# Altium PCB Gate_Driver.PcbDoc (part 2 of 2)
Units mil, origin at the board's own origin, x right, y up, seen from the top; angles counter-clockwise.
Board outline 1574.8 x 1574.8 mil, 2 copper layers (Top Layer, Bottom Layer), stack 62 mil thick; 111 components, 52 nets, 273 pads, 84 vias.
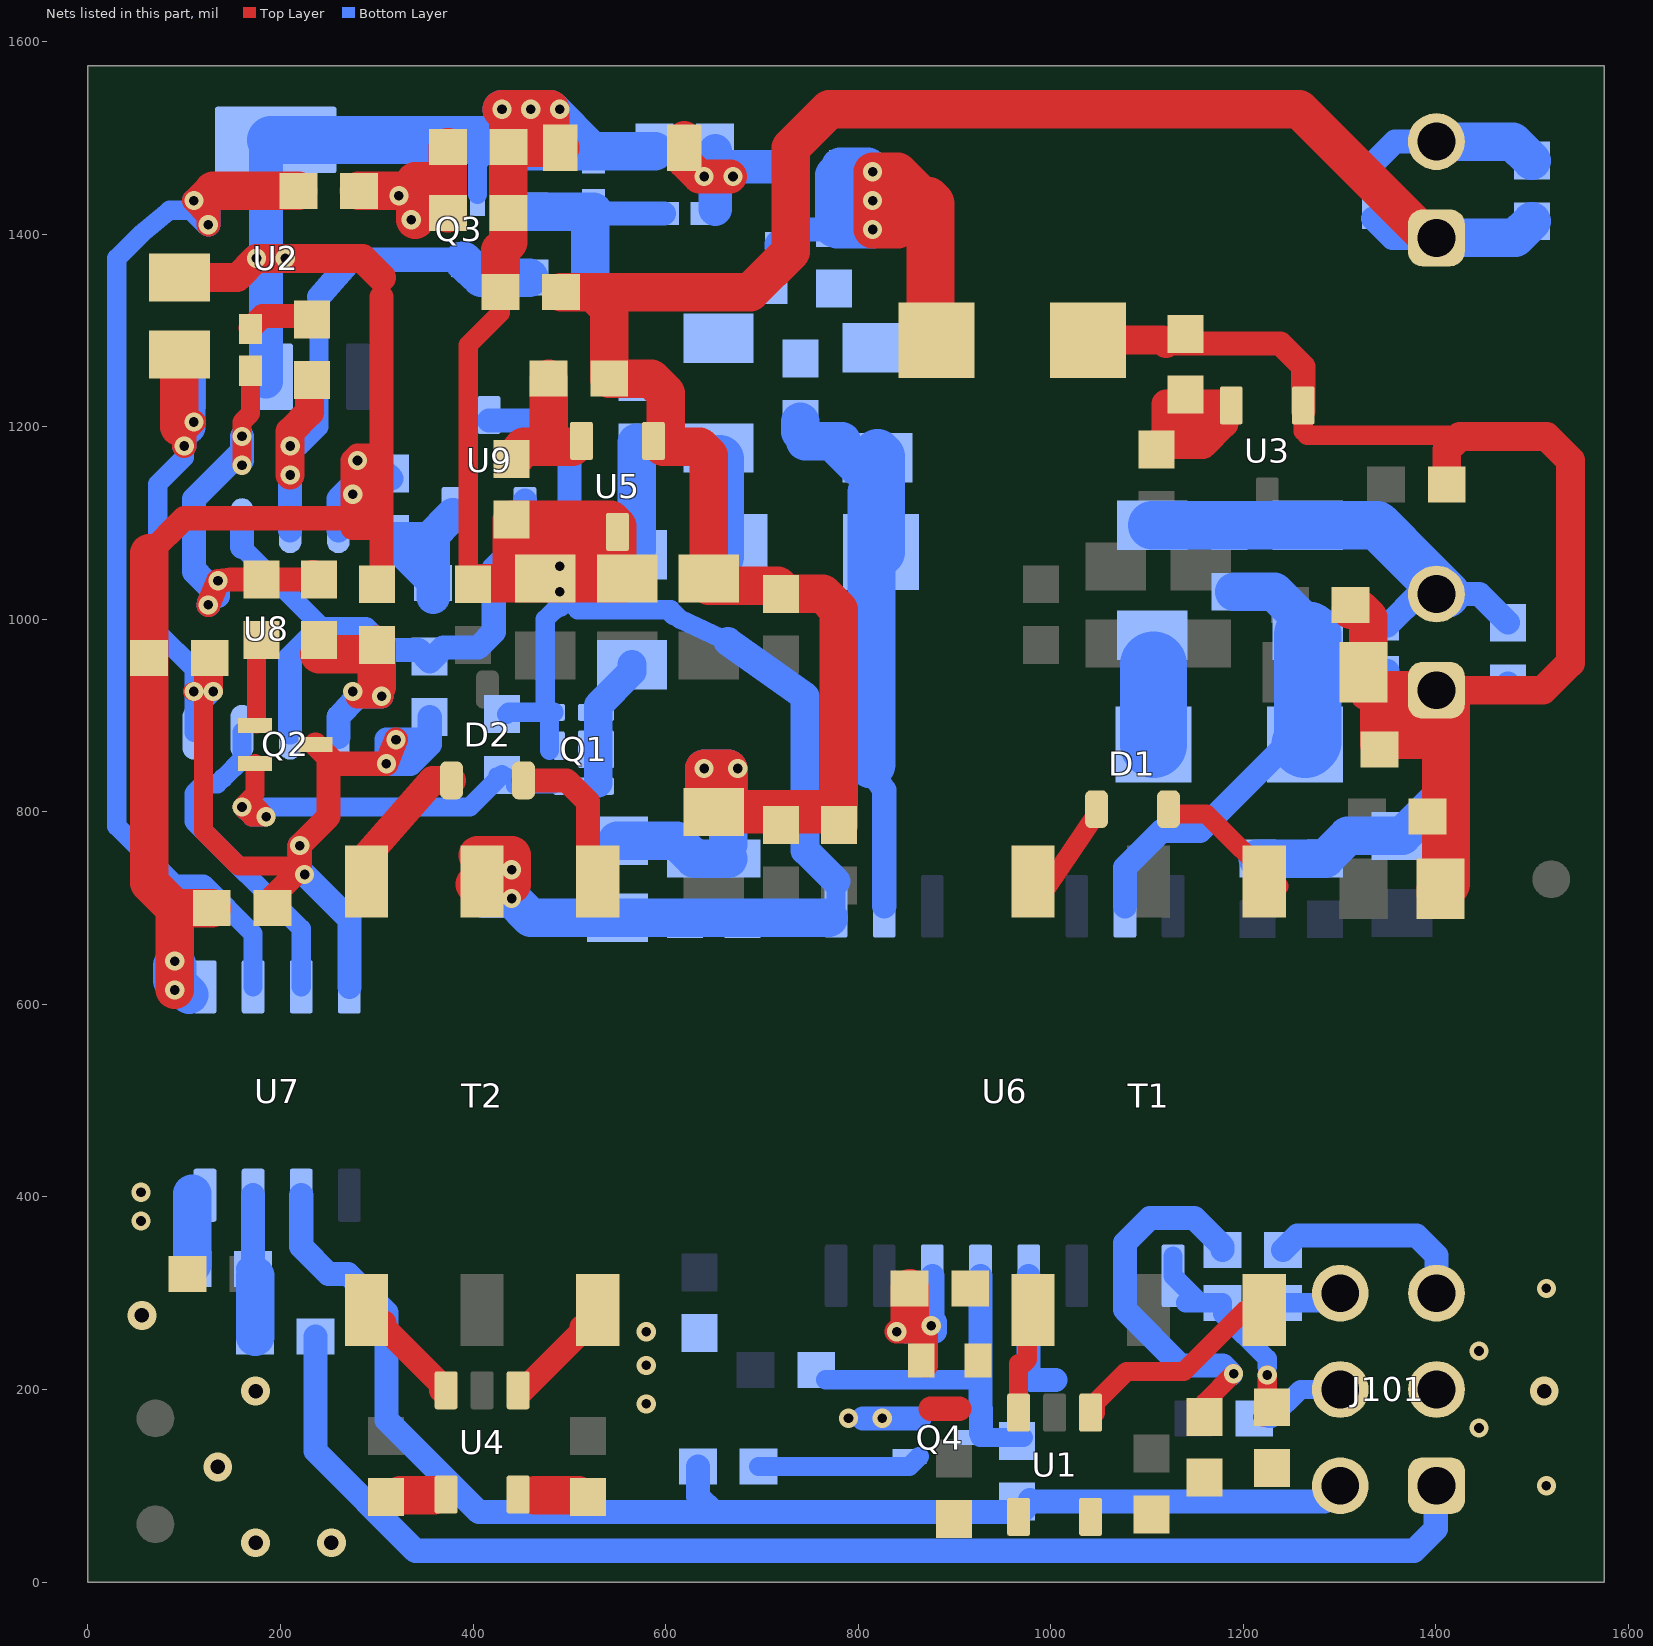
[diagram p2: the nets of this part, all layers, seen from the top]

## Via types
v1: diameter 20, hole 10, Top Layer to Bottom Layer, 78 vias
v2: diameter 30, hole 15, Top Layer to Bottom Layer, 6 vias

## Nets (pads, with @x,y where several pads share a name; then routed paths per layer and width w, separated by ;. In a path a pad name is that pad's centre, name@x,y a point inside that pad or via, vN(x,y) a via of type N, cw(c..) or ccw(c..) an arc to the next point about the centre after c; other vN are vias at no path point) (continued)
-4Vb: C7.2 C12.2 C13.2 C14.2 C15.2 C26.1 C27.1 C30.1 C33.2 C34.2 C36.2 C37.2 C38.2 D9.2 Q1.4 Q1.7 Q3.2 R6.1 R19.2 R25.1 R26.1 R28.1 R29.1 T2.5 U2.2 U2.4 U5.3 U6.9 U7.5 U8.4 U9.3 | length 5391.6
  Top Layer w20: C14.2@400,1036.5 395,1041.5 395,1285 428.5,1318.5 C15.2@428.5,1340
  Top Layer w25: 63.5,1068.5 100,1105 ; 105,1105 275,1105 ; C36.2@300,1036.5 305,1041.5 305,1095 ; 305,1335 305,1170 ; v1(275,1130) 290,1145 ; v1(275,1130) 290,1115 290,1095 ; v1(275,1130) 275,1145 ; v1(275,1130) 275,1095 290,1095 ; 275,1145 290,1145 ; 275,1145 275,1165 280,1170 305,1170 ; 290,1095 305,1095 ; 290,1145 305,1145 ; 305,1095 305,1145 ; 305,1145 305,1170
  Top Layer w30: C7.2@95,1355 155,1355 v1(175,1375) v1(205,1375) 285,1375 305,1355
  Top Layer w40: 63.5,1068.5 C37.2@63.5,960 63.5,726.5 90,700 ; v1(90,615) 90,700 ; C33.2@128.5,700 90,700 ; T2.5@402.01,725 440,725 440,755 T2.5@405,755 ; C14.2@405.95,1037.44 C13.2@445,1037.44 ; C15.2@428.5,1340 428.5,1383.5 436.77,1391.77 C38.2@436.77,1421.89 R29.1@436.77,1490.59 ; R29.1@436.77,1480.59 446.18,1490 D9.2@490.53,1490 D9.2@489.94,1490.59 ; R29.1@436.77,1490.59 D9.2@489.94,1490.59 ; R29.1@436.77,1490.59 436.77,1523.23 v1(430,1530) 455,1530 480,1530 480,1500.53 D9.2@489.94,1490.59 ; 440,1073.98 R6.1@440,1103.5 543.23,1103.5 U5.3@550,1096.73 ; 440,1073.98 440,1042.44 C13.2@445,1037.44 ; 440,1073.98 527.24,1073.98 U5.3@550,1096.73 ; C13.2@445,1037.44 557.56,1037.44 550,1045 U5.3@550,1096.73
  Bottom Layer w20: Q3.2@404.69,1441.5 404.69,1474.69 416.5,1486.5 R25.1@458.5,1486.5 ; R19.2@435,901.46 436.93,903.39 Q1.4@484,903.39 ; 475,906.34 475,1000 490,1015 ; 479.41,863.74 479.41,898.39 ; v1(490,1028.7) 508.7,1010 602.16,1010 ; 608.66,1003.5 602.16,1010 ; 665,976.85 615.28,1000 605.28,1010 602.16,1010 ; U6.9@777.13,701.93 U6.9@777.13,727.87 ; 410,720 430,720 v1(440,710) ; 410,720 410,700 430,700 v1(440,710) ; 410,720 410,750 420,740 v1(440,740) v1(440,710)
  Bottom Layer w25: U8.4@260,1092.28 260,1125 280,1145 ; 280,1150 280,1145 ; 280,1155 306.5,1155 315,1146.5 291.5,1146.5 280,1135 280,1145 ; U9.3@416.57,1206.34 473.07,1206.34 500,1179.41 500,1065 v1(490,1055) v1(490,1028.7) 490,1015
  Bottom Layer w30: v1(175,1375) 185,1375 v1(205,1375) ; 665,976.85 745,920 745,760 U6.9@777.13,727.87
  Bottom Layer w35: U2.2@185,1246.97 185,1375 U2.4@185,1493.03
  Bottom Layer w40: 90,625 105,610 ; v1(430,1530) 455,1530 480,1530 523.5,1486.5 C34.2@525,1486.5 ; v1(440,710) 460,690 465,690 C26.1@550,690 620,690 680,690 U6.9@769.71,690 ; R25.1@458.5,1486.5 R25.1@458.5,1486.5 R26.1@588.5,1486.46
  Bottom Layer w45: 90,625 v1@90,640
  Bottom Layer w50: U2.4@190,1498.03 U2.4@195,1498.03 R25.1@451.97,1498.03
  other v1: 90,645 280,1165 460,1530 490,1530
Coma: C1.2 C8.1 C16.1 C17.1 C18.1 C19.1 C20.1 C21.1 C39.2 D6.1 J103.1 R1.1 R2.2 R12.1 U3.1 | length 2048.7
  Top Layer w20: U3.1@1262.4,1216.34 1262.4,1195.28 1266.34,1191.34 1413.66,1191.34 1420,1185
  Top Layer w25: 1120,1286.5 1238.5,1286.5 1262.4,1262.6 U3.1@1262.4,1216.34
  Top Layer w30: D6.1@1038.74,1290 1116.5,1290 1120,1286.5 ; J103.1@1410.63,926.3 1511.3,926.3 1539.8,954.8 1539.8,1165.2 1515,1190 1425,1190 1420,1185 1411.5,1176.5 C8.1@1411.5,1140
  Top Layer w40: C1.2@1311.5,1010 1321.5,1010 1330,1001.5 R1.1@1330,935 ; R1.1@1325,940 R1.1@1330,935 ; R1.1@1330,925 R1.1@1330,935 ; R1.1@1336.5,928.5 R1.1@1330,935 ; C21.1@1341.5,870 C21.1@1341.5,875 ; R1.1@1341.5,928.5 1341.5,900 ; 1352.8,926.3 J103.1@1410.63,926.3 ; 1410,875 C21.1@1341.5,875 ; 1410.63,896.3 1406.93,900 1341.5,900 ; C21.1@1341.5,875 1341.5,900
  Top Layer w50: C16.1@1405,715 C16.1@1405,720 1410.63,725.63 1410.63,896.3 J103.1@1410.63,926.3
  Bottom Layer w25: C39.2@1350,946.38 1350,941.3 1365,926.3 1467.8,926.3 R12.1@1475,933.5
  Bottom Layer w40: C20.1@1215,751.5 C19.1@1285,751.5 1308.5,775 C18.1@1365,775 1410.63,820.63 J103.1@1410.63,925.67
Comb: C9.2 C15.1 C26.2 C27.2 C28.2 C29.2 C30.2 C31.2 C40.2 J102.1 R4.1 R5.2 R14.1 U5.1 | length 2536.4
  Top Layer w30: C15.1@510.87,1339.21 511.65,1340 ; 527.87,1340 529.37,1338.5
  Top Layer w40: C15.1@491.5,1340 511.65,1340 524.49,1340 ; C28.2@640,810 v1(640,845) 665,845 665,815 C28.2@650,800 ; C9.2@720,1026.5 763.5,1026.5 780,1010 C31.2@780,786.5 ; C9.2@725,1026.5 716.5,1035 645,1035 645,1170 635.59,1179.41 597.4,1179.41 600,1182.01 600,1235 585,1250 R5.2@541.5,1250 541.5,1322.99 524.49,1340 ; J102.1@1410.63,1396.3 1391.89,1396.3 1258.19,1530 770,1530 730,1490 730,1381.87 688.13,1340 527.87,1340 524.49,1340
  Top Layer w45: C28.2@650,800 C31.2@770,800
  Bottom Layer w25: C40.2@1335,1416.38 1355.08,1396.3 J102.1@1410.63,1396.3
  Bottom Layer w40: C26.2@550,770 611.5,770 630,751.5 C27.2@665,751.5 ; v1(640,845) 665,845 C27.2@665,766.5 ; J102.1@1410.63,1396.3 1482.8,1396.3 R14.1@1500,1413.5
  other v1: 675,845
FLT: J101.2 R31.1 R32.2 U7.2 | length 1380
  Bottom Layer w25: U7.2@221.5,401.73 221.5,348.5 250,320 270,320 310,280 310,168.5 406,72.5 650,72.5 ; R32.2@633.5,120 633.5,89 650,72.5 ; R31.1@978.5,85 R31.1@980,83.5 ; J101.2@1300.82,100 1284.32,83.5 R31.1@980,83.5 ; 650,72.5 969,72.5 R31.1@980,83.5
G1: C23.2 C39.1 J103.2 R7.2 R8.2 R12.2 | length 485.1
  Bottom Layer w25: C39.1@1350,993.62 1383.46,1027.09 1383.46,1053.46 ; J103.2@1410.63,1026.3 1445.2,1026.3 R12.2@1475,996.5
  Bottom Layer w50: R8.2@1105.55,1097.76 R7.2@1267.05,1097.76 1339.17,1097.76 1383.46,1053.46 J103.2@1410.63,1026.3
G2: C24.2 C25.1 C40.1 D5.1 J102.2 R10.2 R11.2 R14.2 R15.2 | length 182.6
  Bottom Layer w25: C40.1@1335,1473.62 1357.68,1496.3 J102.2@1410.63,1496.3
  Bottom Layer w40: J102.2@1410.63,1496.3 1480.2,1496.3 R14.2@1500,1476.5
GND: C2.2 C3.2 C10.2 C11.2 C22.2 C32.2 C35.2 C41.2 C42.2 C43.2 J101.3 Q4.2 R9.2 U1.4 U1.5 U4.4 U4.5 U6.4 U7.4 | length 376.9
  Top Layer w25: 875,180 905.47,180
  Top Layer w40: C11.2@324.37,90 359.37,90 ; 464.37,90 C10.2@509.37,90
  Bottom Layer w25: 805,170 805.31,169.69 Q4.2@863.5,169.69 ; U6.4@977.13,318.07 977.13,212.87 980,210 1005,210
  Bottom Layer w40: C35.2@108.5,330 108.5,403.5
  other v1: 1515,100 1445,160 790,170 825,170 580,185 580,225 1445,240 580,260 1515,305 55,375 55,405
  other v2: 174.14,40.8 252.88,40.8 134.77,119.54 174.14,198.28 1512.73,198.28 56.03,277.02
NetC23_1: C23.1 D3.1 R7.1 U6.15 | length 496.2
  Bottom Layer w25: U6.15@1077.13,701.93 1077.13,742.13 1115,780 1155,780 1245,870 D3.1@1264.29,870
  Bottom Layer w30: R7.1@1267.05,983.58 R7.1@1267.05,993.78
  Bottom Layer w40: C23.1@1190.55,1028.68 1232.15,1028.68 R7.1@1267.05,993.78
  Bottom Layer w70: D3.1@1264.29,870 1267.05,872.76 R7.1@1267.05,983.58
NetC24_1: C24.1 D4.1 R10.1 U6.10 | length 626.2
  Bottom Layer w25: 808.74,849.49 827.13,822.87 U6.10@827.13,701.93
  Bottom Layer w40: C24.1@740,1195 C24.1@740,1205.06 ; 745,1185 772.91,1185 ; 782.91,1185 772.91,1185 ; R10.1@800,1157.91 772.91,1185
  Bottom Layer w50: 813.74,849.49 813.74,1131.65 ; R10.1@820,1172.91 823.74,1169.17 D4.1@823.74,1070
NetC25_2: C25.2 R13.2 | length 118.5
  Bottom Layer w40: R13.2@565,1067.09 570,1072.09 C25.2@570,1183.5
NetC34_1: C34.1 D8.1 R21.2 R25.2 | length 210.6
  Bottom Layer w25: C34.1@525,1423.5 527.05,1421.46 D8.1@598.35,1421.46
  Bottom Layer w40: R25.2@458.5,1423.5 525,1423.5 521.5,1420 R21.2@521.5,1355
NetC35_1: C35.1 R23.2 U7.3 | length 141.8
  Bottom Layer w25: C35.1@166.5,325 171.5,330 U7.3@171.5,401.73
  Bottom Layer w40: R23.2@173.5,255 C35.1@173.5,317.99
NetC36_1: C36.1 R22.2 U8.5 | length 205.7
  Top Layer w25: v1@280,920 v1(305,920) ; 295,925 300,930
  Top Layer w40: R22.2@240,963.5 C36.1@295,963.66 ; 300,930 C36.1@300,973.5
  Bottom Layer w25: U8.5@260,877.72 U8.5@260,882.72 260,898.31 280,920 v1(305,920)
  other v1: 275,925
NetC38_1: C38.1 Q3.1 R27.2 R29.2 | length 351
  Top Layer w40: R27.2@281.5,1445 338.78,1445 346.89,1436.89 C38.1@373.78,1436.89 ; v1@340,1415 340,1440 ; 340,1455 364.62,1455 ; C38.1@364.62,1440 373.78,1449.16 ; C38.1@373.78,1421.89 373.78,1449.16 ; R29.2@373.78,1490.59 373.78,1449.16
  Bottom Layer w20: v1(322.95,1440) 335.75,1427.2 ; v1(335.75,1415) 335.75,1427.2 ; 335.75,1440 335.75,1427.2 ; Q3.1@361.81,1440 340,1440 340,1415 343.82,1415 Q3.1@365.32,1436.5
NetC41_1: C41.1 R34.1 U6.2 | length 377.6
  Top Layer w20: C41.1@1160,186.28 v1(1190,216.28)
  Bottom Layer w25: R34.1@1178.5,345 1178.5,348.7 1149.15,378.05 1103.05,378.05 1077.13,352.13 U6.2@1077.13,318.07 1077.13,282.87 1135,225 1178.78,225 v1@1187.5,216.28
NetC42_1: C42.1 R33.1 U6.1 | length 238.2
  Top Layer w20: C42.1@1220,171.5 1225,176.5 v1(1225,215)
  Bottom Layer w10: v1(1225,215) v1@1225,223.7
  Bottom Layer w20: U6.1@1127.13,338.27 U6.1@1127.13,318.07 1155.2,290 ; 1140,290 1155.2,290 ; v1@1225,223.7 1225,231.81 1178.5,278.31 R33.1@1178.5,290 1155.2,290
NetC43_1: C43.1 R9.1 U6.6 | length 267.3
  Top Layer w25: 853.5,273.5 v1(840,260) 850,260 ; 855,270 853.5,268.5 850,265 850,260 ; R9.1@870,234.53 v1@870,260 ; v1@870,265 v1@870,260 ; R9.1@870.47,225 870.47,260.47 v1@870,260 ; 850,260 v1@870,260
  Top Layer w40: 853.5,268.5 853.5,273.5 C43.1@853.5,305
  Bottom Layer w25: 850,260 v1@877.13,260 ; v1@872.13,265 v1@875,265 ; U6.6@877.13,318.07 v1@877.13,267.13 ; v1@880,260 v1@877.13,260 ; v1@880,265 v1@877.13,265 ; v1@880,270 v1@877.13,267.13 ; v1@875,265 v1@877.13,265 ; v1@875,265 v1@877.13,267.13 ; v1@877.13,260 v1@877.13,265 ; v1@877.13,265 v1@877.13,267.13
  other v1: 876.06,266.06
NetD1_1: D1.1 T1.6 | length 90.7
  Top Layer w20: T1.6@996.69,722.64 D1.1@1047.6,797.76
NetD1_2: D1.2 T1.4 | length 145.6
  Top Layer w20: D1.2@1122.4,797.76 1161.73,797.76 T1.4@1236.85,722.64
NetD2_1: D2.1 T2.6 | length 150.6
  Top Layer w30: T2.6@289.29,727.64 289.29,754.29 357.76,832.76 D2.1@377.6,832.76
NetD2_2: D2.2 T2.4 | length 134.2
  Top Layer w25: D2.2@452.4,832.76 497.24,832.76 519.45,810.55 T2.4@519.45,752.64
NetD3_2: D3.2 R8.1 | length 82.6
  Bottom Layer w70: D3.2@1106.81,870 1106.81,952.6
NetD4_2: D4.2 R11.1 | length 101.7
  Bottom Layer w50: D4.2@656.26,1065 R11.1@656.26,1166.65
NetD5_2: D5.2 D6.2 R15.1 R18.2 | length 679
  Top Layer w40: 841.26,1405 v1(815,1405) v1(815,1435) v1(815,1465) 841.26,1465 ; 841.26,1405 841.26,1465 ; 841.26,1405 871.26,1435 841.26,1465
  Top Layer w50: 871.26,1435 875,1431.26 D6.2@875,1285
  Bottom Layer w25: D5.2@715,1386.65 715,1390 730,1405 771.5,1405 R15.1@775,1401.5 ; R18.2@781.5,1470 790,1461.5
  Bottom Layer w40: R15.1@775,1406.5 R18.2@775,1461.5 ; R15.1@778.5,1405 v1(815,1405) v1(815,1435) v1(815,1465) 810,1470 R18.2@781.5,1470
NetD7_1: D7.1 R17.1 | length 65.3
  Top Layer w25: D7.1@168.8,1302.58 181.22,1315 R17.1@229,1315
NetD7_2: D7.2 R16.1 R22.1 U8.1 | length 499.8
  Top Layer w20: v1(160,1160) 160,1205 168.8,1213.8 D7.2@168.8,1258.35 ; R22.1@232.5,1051.5 R22.1@235,1051.5
  Top Layer w25: v1(125,1015) v1@135,1039.45 ; v1(135,1040) 147.95,1041.5 R16.1@180,1041.5 R22.1@240,1041.5
  Bottom Layer w25: 110,1050 110,1049.45 135,1024.45 135,1039.45 v1(125,1015) ; 122.52,1039.45 110,1051.97 U8.1@110,1097.28 110,1125 160,1175 ; v1@160,1165 v1(160,1190)
NetD8_2: D8.2 D9.1 R18.1 R26.2 | length 217.1
  Top Layer w35: D9.1@619.47,1500 619.47,1475.53 635,1460 v1@667,1460
  Bottom Layer w25: v1(640,1460) 651.5,1460 v1@660,1460
  Bottom Layer w35: D8.2@651.5,1426.3 651.5,1460 R26.2@651.5,1486.46 ; 660,1470 R18.1@718.5,1470
  other v1: 670,1460
NetJ101_4: J101.4 R132.1 | length 86.7
  Bottom Layer w20: R132.1@1226.5,170 1229.5,170 1259.5,200 J101.4@1300.82,200
NetQ1_1: Q1.1 Q1.2 Q1.5 Q1.6 Q1.8 R13.1 | length 137.4
  Bottom Layer w30: 530,830 530,910.51 565,945.51 R13.1@565,952.91
NetQ1_3: Q1.3 Q2.2 R19.1 | length 502.2
  Top Layer w20: Q2.2@173.5,850.31 173.5,818.5 v1(160,805) ; v1(160,805) 175,805 v1(185,795) 170,795 v1(160,805)
  Bottom Layer w15: R19.1@423.47,838.47 R19.1@430,838.47 435,838.47 R19.1@446.85,826.61 ; R19.1@441.85,826.61 R19.1@446.85,826.61 ; Q1.3@484.41,826.61 R19.1@446.85,826.61
  Bottom Layer w20: 180,805 396.53,805 R19.1@430,838.47 ; v1(160,805) 175,805 v1(185,795) 170,795 v1(160,805)
NetQ2_1: Q2.1 R16.2 | length 87.3
  Top Layer w20: Q2.1@175,891.18 R16.2@175,978.5
NetQ3_3: Q3.3 R17.2 R21.1 U8.3 | length 596.8
  Top Layer w30: v1(210,1150) v1(210,1180) 210,1195 230,1215 230,1246 R17.2@232.5,1248.5
  Bottom Layer w20: 220,1180 240,1200 240,1335
  Bottom Layer w25: U8.3@210,1092.28 U8.3@210,1097.28 v1(210,1150) v1(210,1180) ; 240,1335 273.5,1373.5 Q3.3@385,1373.5
  Bottom Layer w40: Q3.3@390,1372.52 408.5,1355 R21.1@458.5,1355
NetQ4_1: Q4.1 R32.1 | length 171.3
  Bottom Layer w20: R32.1@696.5,120 853.19,120 Q4.1@863.5,130.32
NetQ4_3: Q4.3 R30.1 R31.2 U6.5 | length 368.7
  Bottom Layer w20: R30.1@766.5,210 927.13,210 ; Q4.3@926.5,150 R31.2@971.5,150
  Bottom Layer w25: U6.5@927.13,318.07 927.13,210 Q4.3@927.48,155
NetR2_1: R2.1 R3.2 U3.2 | length 256.9
  Top Layer w30: 1157.99,1212.71 1157.99,1207.99 ; 1173.5,1223.5 1120,1223.5 ; U3.2@1180,1203.5 1157.99,1181.5 ; 1120,1223.5 1138.5,1205 1155,1205 1157.99,1207.99 ; 1120,1223.5 1120,1191.5 1110,1181.5 1157.99,1181.5 ; 1157.99,1181.5 1157.99,1207.99
NetR5_1: R5.1 R6.2 U5.2 | length 127.4
  Top Layer w40: R6.2@445,1170 452.91,1179.41 U5.2@503,1179.41 ; 478.5,1185 R5.1@478.5,1250
NetR20_1: R20.1 R24.2 U8.2 U8.6 U9.1 | length 613.2
  Bottom Layer w20: U8.2@160,1075 240,995
  Bottom Layer w25: U8.2@160,1075 U8.2@160,1097.28 ; U8.6@210,882.72 210,960 240,990 288.35,990 310,968.35 343.15,968.35 355,956.5 369.06,970.55 405,970.55 421.5,987.05 R24.2@421.5,1037.8 421.5,1052.95 453.97,1085.43 U9.1@453.97,1123.66
NetR24_1: R24.1 R28.2 U9.2 | length 198.7
  Bottom Layer w35: R24.1@358.5,1022.8 R24.1@358.5,1040 ; U9.2@379.17,1108.66 354.01,1083.5 ; 354.01,1083.5 358.5,1079.01 R24.1@358.5,1040 ; 354.01,1083.5 315,1083.5 R24.1@358.5,1040
NetR27_1: R27.1 U7.6 | length 1200.7
  Top Layer w25: v1(125,1410) 125,1420 ; 125,1420 v1(110,1435) 120,1445 130,1445 125,1440 125,1420
  Top Layer w40: 130,1445 R27.1@218.5,1445
  Bottom Layer w20: 115,1425 110,1425 85,1425 55,1400 30,1375 30,785 90,725 120,725 171.5,673.5 U7.6@171.5,618.27
  Bottom Layer w25: v1(110,1435) 125,1435 125,1420 ; v1(110,1435) 125,1420 ; v1(110,1435) 110,1425 v1(125,1410) 125,1420
NetT1_1: T1.1 U1.3 | length 102.6
  Top Layer w20: U1.3@966.66,185.94 966.66,226.74 ; 971.66,226.74 976.02,231.11 976.02,271.69 T1.1@986.69,282.36
NetT1_3: T1.3 U1.1 | length 230.6
  Top Layer w20: U1.1@1046.46,175.94 1046.46,186.46 1078.68,218.68 1138.29,218.68 1201.97,282.36 T1.3@1226.85,282.36
NetT2_1: T2.1 U4.3 | length 118.3
  Top Layer w25: T2.1@289.29,272.36 289.29,269.34 T2.1@307.71,269.34 ; T2.1@302.71,269.34 366.97,205.08 U4.3@366.97,199.13
NetT2_3: T2.3 U4.1 | length 117.3
  Top Layer w25: U4.1@451.77,199.13 T2.3@517.72,265.08 ; T2.3@512.72,265.08 529.45,265.08 T2.3@529.45,272.36
NetU7_7: U7.7 U8.7 | length 339.9
  Bottom Layer w20: U8.7@160,882.72 160,854.5 140.5,835 140,835 134.17,829.17 120,829.17 110,819.17 110,790 221.5,678.5 U7.7@221.5,618.27
RESET: J101.1 R23.1 | length 1380
  Bottom Layer w25: R23.1@236.5,255 236.5,136 340,32.5 1377.5,32.5 1400,55 1400,99.18 J101.1@1400.82,100
Vcc5V: C7.1 C33.1 C37.1 Q2.3 R20.2 U2.3 U7.8 U8.8 | length 1496.5
  Top Layer w20: v1@108.5,925 v1(110,925) v1@120,925 ; C37.1@126.5,960 C37.1@120,953.5 ; v1@220,740 216.3,743.7 156.3,743.7 120,780 v1@120,925 ; v1@120,925 v1(130,925) 130,943.5 C37.1@120,953.5 ; v1@120,925 C37.1@120,953.5
  Top Layer w25: v1(100,1180) 100,1195 v1(110,1205) ; C33.1@191.5,700 191.5,711.5 220,740 v1(220,765) 250,795 250,850 ; Q2.3@236.5,870 256.5,850 v1(310,850) v1(320,875)
  Top Layer w40: 95,1200 C7.1@95,1255
  Bottom Layer w20: v1(100,1180) 100,1168.03 72.5,1140.53 72.5,986.42 110,948.92 v1(110,925) ; U8.8@110,882.72 U8.8@110,905 ; U8.8@110,905 v1(110,925) ; U8.8@110,905 v1(130,925) v1(110,925)
  Bottom Layer w25: v1(100,1180) 100,1195 104.45,1199.45 v1(110,1205) ; v1(220,765) 220,740 271.5,688.5 U7.8@271.5,618.27 ; 354.97,870.02 349.98,875 310,875 v1(310,850) 335,850 355,870 R20.2@355,898.5
  Bottom Layer w35: v1@104.45,1199.45 U2.3@104.45,1251.97
  other v1: 225,735
Vg1: J101.6 R33.2 | length 49.3
  Bottom Layer w20: R33.2@1241.5,290 J101.6@1290.82,290
Vg2: J101.5 R34.2 | length 213.3
  Bottom Layer w25: R34.2@1241.5,345 1256.5,360 1380,360 1400.82,339.18 J101.5@1400.82,300
pads on no net: FID1.1 FID2.1 FID3.1 Q1.0 U6.7

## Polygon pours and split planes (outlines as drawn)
G2 on Bottom Layer "BOTTOM_LAYER_G2_P000" (solid, remove dead copper, pour order 0): 555,1250 895,1250 935,1290 935,1355 1045,1465 1425,1465 1440,1480 1440,1515 1420,1535 1010,1535 875,1400 875,1375 855,1355 660,1355 625,1320 585,1320 555,1290
5Vin on Bottom Layer "BOTTOM_LAYER_5VIN_P004" (solid, remove dead copper, pour order 4): 315,430 405,340 765.87,340 775,330.87 775,290 770,285 668.7,285 653.7,300 505,300 465,260 370,260 355,275 355,320 300,375 265,375 255,385 255,425 260,430
GND on Bottom Layer "BOTTOM_LAYER_GND_P006" (solid, remove dead copper, pour order 6): 0,430 297.52,430 380,347.52 1572.28,347.52 1574.8,345 1574.8,5 0,5 0,420 0,425
Comb on Top Layer "TOP_LAYER_COMB_P014" (solid, remove dead copper, pour order 14): 798.54,770 808.54,780 808.54,1041.46 625,1225 625,1350 605,1370 481.3,1370 470,1358.7 470,1330 515,1285 515,1250 570,1195 570,1160 611.26,1118.74 611.26,788.74 630,770
Coma on Top Layer "TOP_LAYER_COMA_P012" (solid, remove dead copper, pour order 12): 1000,1250 1075,1250 1100,1275 1230,1275 1250,1255 1250,1195 1260,1185 1390,1185 1400,1175 1470,1175 1495,1150 1495,961.3 1488.7,955 1365,955 1350,970 1350,1005 1345,1005 1325,1025 1295,1025 1290,1020 1290,925 1320,895 1320,850 1325,845 1364.98,845 1369.98,840 1369.98,695.02 1380,685 1574.8,685 1574.8,1150.2 1520,1205 1340,1205 1218.98,1326.02 1000,1326.02
5Vin on Top Layer "TOP_LAYER_5VIN_P010" (solid, remove dead copper, pour order 10): 455,320 460,315 460,270 435,245 385,245 360,270 360,315 365,320
GND on Top Layer "TOP_LAYER_GND_P008" (solid, remove dead copper, pour order 8): 0,430 297.52,430 397.52,330 1574.8,330 1574.8,5 0,5 0,420 0,425

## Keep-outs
Keep-Out Layer:
  lines w10: 0,0 0,1574.8 1574.8,1574.8 1574.8,0 0,0 ; 65,470 65,540 1355,540 1355,470 65,470
  text ".Layer_Name" at 597,-858.49 h60

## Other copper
Top Layer:
  text ".Layer_Name" at 597,-858.49 h60
Bottom Layer:
  text ".Layer_Name" at 597,-858.49 h60

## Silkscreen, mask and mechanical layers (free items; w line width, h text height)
Top Overlay:
  lines w10: 10,500 50,500
  text "S2 G2" at 1340,1365 h35 r90
  text "S1 G1" at 1550,1105 h35 r90
  text ".Layer_Name" at 597,-858.49 h60
Bottom Overlay:
  lines w10: 10,500 50,500 ; 1375,500 1555,500
  text ".Layer_Name" at 597,-858.49 h60
Top Paste:
  text ".Layer_Name" at 597,-858.49 h60
Bottom Paste:
  text ".Layer_Name" at 597,-858.49 h60
Top Solder:
  text ".Layer_Name" at 597,-858.49 h60
  text ".Layer_Name" at 597,-858.49 h60
Bottom Solder:
  text ".Layer_Name" at 597,-858.49 h60
Drill Guide:
  text ".Layer_Name" at 597,-858.49 h60
M1 Board Outline:
  lines w10: 0,0 0,1574.8 1574.8,1574.8 1574.8,0 0,0 ; 65,470 65,540 1355,540 1355,470 65,470
  text ".Layer_Name" at 597,-858.49 h60
M2 Board Dimensions:
  rectangle: 20,-275 145,-150
  rectangle: 145,-400 520,-275
  lines w7: 20,-275 1020,-275 ; 145,-400 145,-150 ; 270,-400 270,-150 ; 520,-400 520,-150 ; 770,-400 770,-150 ; 20,-400 1020,-400 1020,-150 20,-150 20,-400
  text ".Layer_Name" at 597,-858.49 h60
M3 3D STEP Top:
  text ".Layer_Name" at 597,-858.49 h60
M4 3D STEP Bottom:
  text ".Layer_Name" at 597,-858.49 h60
M5 Assembly Top:
  lines w10: -272,-930.17 6328,-930.17 ; -272,-726.83 6330,-726.83 ; -272,-523.5 -272,-1133.5 3733,-1133.5 6330,-1133.5 6330,-523.5 -271.5,-523.5 -271.5,-1133.5 1304,-1133.5 ; 2193,-1133.5 2193,-523.5 ; 3460,-726.83 3460,-523.5 ; 4300,-726.83 4300,-523.5 ; 4922,-1140 4922,-937.17
  text "COMPONENTS MARKED 'DNP' SHOULD NOT BE POPULATED." at 1173.5,-318.5 h60
  text "ASSEMBLY VARIANT:" at 1173,-434 h60
  text ".VariantName" at 2209,-434 h60
  text "PCB VIEWED FROM TOP SIDE" at -208.5,-655.67 h60
  text "BOARD #:" at 2268,-655.67 h60
  text ".PRJ_Number" at 2813.5,-655.67 h60
  text "REV:" at 3658,-655.67 h60
  text ".PCB_Rev" at 3949.5,-655.67 h60
  text "SVN REV:" at 4496,-655.67 h60
  text ".VersionControl_RevNumber" at 5002,-655.67 h60
  text "TID #:" at 2268,-859 h60
  text ".TID" at 2813.5,-859 h60
  text "PLOT NAME =" at -208.5,-1064.34 h60
  text ".plot_File_Name" at 597,-1064.34 h60
  text "GENERATED    :" at 2270,-1064.34 h60
  text ".Print_Date" at 3139.5,-1064.34 h60
  text ".Print_Time" at 3868.5,-1064.34 h60
  text "TEXAS INSTRUMENTS" at 5133,-1064.34 h60
M6 Assembly Bottom:
  lines w10: -272.5,-727.33 6329.5,-727.33 ; -270.5,-930.67 6329.5,-930.67 ; 1135.5,-1140.5 1135.5,-937.67 ; 1757.5,-727.33 1757.5,-524 ; 2597.5,-727.33 2597.5,-524 ; 3864.5,-1134 3864.5,-524 ; 4753.5,-1134 6329,-1134 6329,-524 -272.5,-524 -272.5,-1134 2324.5,-1134 6329.5,-1134 6329.5,-524
  text "COMPONENTS MARKED 'DNP' SHOULD NOT BE POPULATED." at 6122,-318 h60
  text ".VariantName" at 5078,-434 h60
  text "ASSEMBLY VARIANT:" at 6117,-434 h60
  text ".VersionControl_RevNumber" at 1055.5,-656.17 h60
  text "SVN REV:" at 1561.5,-656.17 h60
  text ".PCB_Rev" at 2108,-656.17 h60
  text "REV:" at 2399.5,-656.17 h60
  text ".PRJ_Number" at 3244,-656.17 h60
  text "BOARD #:" at 3789.5,-656.17 h60
  text "PCB VIEWED FROM BOTTOM SIDE" at 6266,-656.17 h60
  text ".TID" at 3244,-859.5 h60
  text "TID #:" at 3789.5,-859.5 h60
  text "TEXAS INSTRUMENTS" at 924.5,-1064.84 h60
  text ".Print_Time" at 2189,-1064.84 h60
  text ".Print_Date" at 2918,-1064.84 h60
  text "GENERATED    :" at 3787.5,-1064.84 h60
  text ".plot_File_Name" at 5460.5,-1064.84 h60
  text "PLOT NAME =" at 6266,-1064.84 h60
M9 Title Sheet:
  drawing of 57 lines, arcs and shapes, not listed
  text "1" at 759.84,8036.5 h70
  text "2" at 3255.5,8036.5 h70
  text "3" at 5744.84,8036.5 h70
  text "4" at 8251.51,8036.5 h70
  text "5" at 10750.5,8036.5 h70
  text "6" at 13255.5,8036.5 h70
  text "A" at -396.5,6893.5 h70
  text "A" at 14403.5,6893.5 h70
  text "B" at -396.5,4513.5 h70
  text "B" at 14403.5,4513.5 h70
  text "C" at -396.5,2138.5 h70
  text "C" at 14403.5,2138.5 h70
  text "PROJECT TITLE:" at 11363.5,277.5 h45
  text ".PRJ_Title" at 11413.5,144.17 h70
  text "DESIGNED FOR:" at 11363.5,-23.5 h45
  text ".PRJ_Customer" at 11413.5,-163.5 h70
  text "D" at -396.5,-231.5 h70
  text "D" at 14403.5,-231.5 h70
  text "FILE NAME:" at 11363.5,-323.5 h45
  text ".PCB_File_Name_No_Path" at 11413.5,-443.5 h70
  text "Texas Instruments (TI) and/or its licensors do not warrant the accuracy or completeness of this specification" at 6394,-605.34 h45
  text "ENGINEER:" at 11363.5,-613.5 h45
  text "LAYOUT BY:" at 12868.5,-613.5 h45
  text "or any information contained therein. TI and/or its licensors do not warrant that this design will meet" at 6349.01,-718 h45
  text ".PRJ_Engineer" at 11413.5,-768.49 h70
  text ".PCB_Layout" at 12919,-768.49 h70
  text "the specifications, will be suitable for your application or fit for any particular purpose, or will operate in" at 6349.01,-830.67 h45
  text ".Layer_Name" at 597,-858.49 h60
  text "ALTIUM DESIGNER VERSION:" at 12868.5,-923.5 h45
  text "an implementation. TI and/or its licensors do not warrant that the design is production worthy. You should" at 6349.01,-943.33 h45
  text "completely validate and test your design implementation to confirm the system functionality for your application." at 6394,-1056 h45
  text ".print_Scale" at 11413.5,-1056.83 h70
  text ".Application_BuildNumber" at 12919,-1056.83 h70
  text "1" at 759.84,-1263.5 h70
  text "2" at 3255.5,-1263.5 h70
  text "3" at 5744.84,-1263.5 h70
  text "4" at 8251.51,-1263.5 h70
  text "5" at 10750.5,-1263.5 h70
  text "6" at 13255.5,-1263.5 h70
M10 Fab Notes:
  drawing of 189 lines, arcs and shapes, not listed
  text "DESIGN INFORMATION" at 12402.02,6356.17 h60
  text "MIN. TRACK WIDTH:" at 11757.46,6224.05 h60
  text "8" at 12853.7,6224.05 h60
  text "MIL" at 13008.46,6224.05 h60
  text "MIN. CLEARANCE:" at 11757.46,6099.92 h60
  text "0.2" at 12793.7,6099.93 h60
  text "mm" at 13008.46,6099.92 h60
  text "MIN. VIA PAD SIZE:" at 11757.46,5975.8 h60
  text "24" at 12823.71,5975.8 h60
  text "MIL" at 13008.46,5975.8 h60
  text "0.05mm (2MIL)" at 12452.46,5845.9 h60
  text "MINIMUM ANNULAR RING" at 11428.23,5837.67 h60
  text "EXTERNAL" at 13160.46,5837.67 h60
  text "PER" at 11628.23,5727.55 h60
  text "IPC-D-275 CLASS 2 LEVEL C" at 11848.23,5727.54 h60
  text "MIL, HOLES" at 13336.46,5627.07 h60
  text "+/-" at 12944,5618.48 h60
  text "+/-" at 13798,5618.48 h60
  text "REGISTRATION TOLERANCES:" at 11428.23,5617.42 h60
  text "METAL" at 12628,5617.42 h60
  text "5" at 13204.2,5617.42 h60
  text "3" at 14037.2,5617.42 h60
  text "MIL" at 14153.46,5617.42 h60
  text "HOLE SIZE TOLERANCE (UNLESS OTHERWISE SPECIFIED):" at 11428.23,5519.1 h60
  text "+/-" at 13798,5516.23 h60
  text "3" at 14037.2,5515.17 h60
  text "MIL" at 14153.46,5515.17 h60
  text "MATERIAL:" at 11353.46,5377.52 h60
  text "FR-4 High Tg" at 12339.9,5249 h60
  text "X" at 12195.46,5241.01 h60
  text "FR-408" at 11774.46,5236.49 h60
  text "OTHER" at 13262.46,5236.49 h60
  text "62 MIL (1.6mm) +/-10%" at 12094.56,5093.46 h60
  text "X" at 11974.46,5091.01 h60
  text "THICKNESS:" at 11428.23,5085.24 h60
  text "OTHER" at 13379.46,5085.24 h60
  text "TOLERANCE:" at 11428.23,4946.92 h60
  text "X" at 12276.46,4946.92 h60
  text "ANSI IPC-6012 TYPE 3 CLASS 2" at 12454.48,4946.92 h60
  text "OTHER +/-" at 12454.46,4802.73 h60
  text "BOW & TWIST:" at 11428.23,4657.54 h60
  text "X" at 12276.46,4657.54 h60
  text "ANSI IPC-6012 TYPE 3 CLASS 2" at 12454.48,4657.54 h60
  text "OTHER +/-" at 12454.46,4510.85 h60
  text "DRILLING:" at 11353.46,4380.23 h60
  text "NC_DRILL FILES" at 13114.46,4275.04 h60
  text "REFERENCE:" at 11428.23,4271.1 h60
  text "X" at 12085.46,4271.01 h60
  text "AS SHOWN" at 12263.46,4271.1 h60
  text "X" at 12986.46,4271.1 h60
  text "OTHER" at 13412.46,4128.85 h60
  text "PTH COPPER THICKNESS:" at 11427.91,4125.32 h60
  text "X" at 12567.14,4125.32 h60
  text "20-30 um" at 12695.14,4125.32 h60
  text "BOARD FINISH:" at 11353.46,3977.73 h60
  text "SILKSCREEN:" at 11508.68,3867.6 h60
  text "X" at 12466.46,3867.6 h60
  text "TOP" at 12583.46,3867.6 h60
  text "X" at 12976.46,3867.6 h60
  text "BOTTOM" at 13094.46,3867.6 h60
  text "SILKSCREEN COLOR:" at 11508.68,3712.41 h60
  text "X" at 12465.46,3712.41 h60
  text "WHITE" at 12583.46,3712.41 h60
  text "OTHER" at 13094.46,3712.41 h60
  text "X" at 12596.46,3568.96 h60
  text "GREEN" at 12714.46,3568.96 h60
  text "OTHER" at 13332.46,3568.96 h60
  text "SOLDER RESIST COLOR:" at 11508.68,3562.1 h60
  text "X" at 12596.46,3414.71 h60
  text "MATTE" at 12714.46,3414.71 h60
  text "SEMI-GLOSS" at 13332,3414.07 h60
  text "IMMERSION GOLD (ENIG)" at 12414.46,3241.94 h60
  text "ENEPIG" at 13752,3234.72 h60
  text "SURFACE FINISH:" at 11353.46,3233.72 h60
  text "X" at 12236.46,3233.72 h60
  text "IMM. TIN/SILVER OR EQUIV" at 11683,3096.4 h60
  text "OTHER" at 13114.46,3092.47 h60
  text "ARRAY/PANEL:" at 11353.46,2937.09 h60
  text "CUT AND TRIM PER M1 BOARD OUTLINE" at 12414.46,2928.87 h60
  text "N.C. ROUTE" at 12414.46,2792.9 h60
  text "X" at 13102.46,2792.9 h60
  text "V. SCORE" at 13280.46,2792.9 h60
  text "CERTIFICATION:" at 11353.46,2663.77 h60
  text "MATERIALS AND WORKMANSHIP FOR ALL PCBS" at 12078.46,2663.77 h60
  text "TO MEET OR EXCEED THE REQUIREMENTS OF:" at 12078.46,2569.71 h60
  text "X" at 11715.97,2441.08 h60
  text "ANSI IPC-A-600F CLASS ->" at 11843.96,2441.08 h60
  text "X" at 13491.97,2441.08 h60
  text "2" at 13601.96,2441.08 h60
  text "1" at 13286.96,2439.58 h60
  text "3" at 13955.96,2439.58 h60
  text "X" at 12527.97,2293.39 h60
  text "RoHS" at 12655.96,2293.39 h60
  text "OTHER" at 13300.36,2293.39 h60
  text "PER ORDER" at 13697.42,2293.39 h60
  text "ALL BOARDS MUST MEET OR EXCEED UL94-V0 REQUIREMENTS." at 11381,2139.57 h60
  text "PCB MUST BEAR THE UL94V-0 UL REGISTERED MATERIAL ID NUMBER" at 11381,2023.5 h60
  text "ADDITIONAL REQUIREMENTS:" at 11353.46,1854.08 h60
  text "MICROSECTION:" at 11428.23,1746.95 h60
  text "YES" at 12333.96,1746.95 h60
  text "REQUIRED" at 13195.46,1602.62 h60
  text "BARE BOARD ELEC. TEST:" at 11428.23,1599.76 h60
  text "NONE" at 12733.96,1599.76 h60
  text "X" at 13077.46,1599.76 h60
  text "PER ORDER" at 13787.46,1599.76 h60
  text "XX MIL VIAS REQUIRE NON-CONDUCTIVE FILL AND PLANARIZE" at 11596.38,1394.82 h59
  text "XX MIL VIAS REQUIRE CONDUCTIVE FILL AND PLANARIZE" at 11604.38,1290.84 h60
  text "OUTER XX MIL VIAS REQUIRE 50 OHM SINGLE-ENDED IMPEDANCE" at 11603.39,1127.46 h58
  text "LAYER 2 & 3 (INNER LAYERS) XX MIL WIDE, XX MIL SPACE / TRACES REQUIRE 100 OHM DIFFERENTIAL IMPEDANCE" at 11595.39,891.74 h60
  text ".Layer_Name" at 597,-858.49 h60
M11 Gerber Information:
  lines w10: -272,-930.17 6328,-930.17 ; -272,-726.83 6330,-726.83 ; -272,-523.5 -272,-1133.5 3733,-1133.5 6330,-1133.5 6330,-523.5 -271.5,-523.5 -271.5,-1133.5 1304,-1133.5 ; 2193,-1133.5 2193,-523.5 ; 3460,-726.83 3460,-523.5 ; 4300,-726.83 4300,-523.5 ; 4922,-1140 4922,-937.17
  text "ALL ARTWORK VIEWED FROM TOP SIDE" at -208.5,-655.67 h60
  text "BOARD #:" at 2268,-655.67 h60
  text ".PRJ_Number" at 2813.5,-655.67 h60
  text "REV:" at 3658,-655.67 h60
  text ".PCB_Rev" at 3949.5,-655.67 h60
  text "SVN REV:" at 4496,-655.67 h60
  text ".VersionControl_RevNumber" at 5002,-655.67 h60
  text "LAYER NAME =" at -208.5,-858.49 h60
  text "TID #:" at 2268,-859 h60
  text ".TID" at 2813.5,-859 h60
  text "PLOT NAME =" at -208.5,-1064.34 h60
  text ".plot_File_Name" at 597,-1064.34 h60
  text "GENERATED    :" at 2270,-1064.34 h60
  text ".Print_Date" at 3139.5,-1064.34 h60
  text ".Print_Time" at 3868.5,-1064.34 h60
  text "TEXAS INSTRUMENTS" at 5133,-1064.34 h60
M12 Stackup:
  drawing of 191 lines, arcs and shapes, not listed
  text "Layer" at 9817.84,7830 h60
  text "Name" at 10227.76,7830 h60
  text "Material" at 11157.5,7830 h60
  text "Thickness" at 12017.27,7830 h60
  text "Constant" at 12667.1,7830 h60
  text "Board Layer Stack" at 13236.96,7830 h60
  text "1" at 9817.84,7710 h60
  text "Top Overlay" at 10227.76,7710 h60
  text "2" at 9817.84,7590 h60
  text "Top Solder" at 10227.76,7590 h60
  text "Solder Resist" at 11157.5,7590 h60
  text "0.40mil" at 12017.27,7590 h60
  text "3.5" at 12667.1,7590 h60
  text "3" at 9817.84,7470 h60
  text "Top Layer" at 10227.76,7470 h60
  text "Copper" at 11157.5,7470 h60
  text "1.40mil" at 12017.27,7470 h60
  text "4" at 9817.84,7350 h60
  text "Dielectric 1" at 10227.76,7350 h60
  text "FR-4" at 11157.5,7350 h60
  text "59.20mil" at 12017.27,7350 h60
  text "4.8" at 12667.1,7350 h60
  text "5" at 9817.84,7230 h60
  text "Bottom Layer" at 10227.76,7230 h60
  text "Copper" at 11157.5,7230 h60
  text "1.40mil" at 12017.27,7230 h60
  text "6" at 9817.84,7110 h60
  text "Bottom Solder" at 10227.76,7110 h60
  text "Solder Resist" at 11157.5,7110 h60
  text "0.40mil" at 12017.27,7110 h60
  text "3.5" at 12667.1,7110 h60
  text "7" at 9817.84,6990 h60
  text "Bottom Overlay" at 10227.76,6990 h60
  text ".Layer_Name" at 597,-858.49 h60
M13 Component Bodies Top:
  text ".Layer_Name" at 597,-858.49 h60
M14 Component Bodies Bottom:
  text ".Layer_Name" at 597,-858.49 h60
M15 Courtyards Top:
  text ".Layer_Name" at 597,-858.49 h60
M16 Courtyards Bottom:
  text ".Layer_Name" at 597,-858.49 h60
Drill Drawing:
  circle w10: c5368.72,3141.96 r27.63
  lines w10: 5341.09,3045.27 5396.34,3045.27 5368.72,2990.02 5341.09,3045.27 ; 5341.09,3238.66 5396.34,3238.66 5396.34,3293.91 5341.09,3293.91 5341.09,3238.66
  lines w12: 5291,2952.72 8522.49,2952.72 ; 5291,3325.68 8522.49,3325.68 ; 5628.86,2828.4 5628.86,3450 ; 5960.86,2828.4 5960.86,3450 ; 6597.43,2828.4 6597.43,3450 ; 6856.57,2828.4 6856.57,3450 ; 7231.72,2828.4 7231.72,3450 ; 7956.05,2828.4 7956.05,3450 ; 5291,2828.4 8522.49,2828.4 8522.49,3450 5291,3450 5291,2828.4
  text "Symbol" at 5365.59,3362.98 h72
  text "Quantity" at 5666.16,3362.98 h72
  text "Finished Hole Size" at 5998.16,3362.98 h72
  text "Plated" at 6634.72,3362.98 h72
  text "Hole Type" at 6893.86,3362.98 h72
  text "Drill Layer Pair" at 7269.02,3362.98 h72
  text "Hole Tolerance" at 7993.35,3362.98 h72
  text "78" at 5666.16,3238.66 h60
  text "10.00mil (0.254mm)" at 5998.16,3238.66 h60
  text "PTH" at 6634.72,3238.66 h60
  text "Round" at 6893.86,3238.66 h60
  text "Top Layer - Bottom Layer" at 7269.02,3238.66 h60
  text "6" at 5666.16,3114.34 h60
  text "15.00mil (0.381mm)" at 5998.16,3114.34 h60
  text "PTH" at 6634.72,3114.34 h60
  text "Round" at 6893.86,3114.34 h60
  text "Top Layer - Bottom Layer" at 7269.02,3114.34 h60
  text "10" at 5666.16,2990.02 h60
  text "39.37mil (1.000mm)" at 5998.16,2990.02 h60
  text "PTH" at 6634.72,2990.02 h60
  text "Round" at 6893.86,2990.02 h60
  text "Top Layer - Bottom Layer" at 7269.02,2990.02 h60
  text "94 Total" at 5666.16,2865.7 h60
  text ".Layer_Name" at 597,-858.49 h60
M17 Embedded Cavity:
  text ".Layer_Name" at 597,-858.49 h60
M18 Embedded Assembly:
  text ".Layer_Name" at 597,-858.49 h60
M19 Embedded Keepout:
  text ".Layer_Name" at 597,-858.49 h60

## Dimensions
20,-400 to 1020,-400 on M2 Board Dimensions
0,0 to 0,1574.8 on M2 Board Dimensions
0,0 to 1574.8,0 on M2 Board Dimensions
